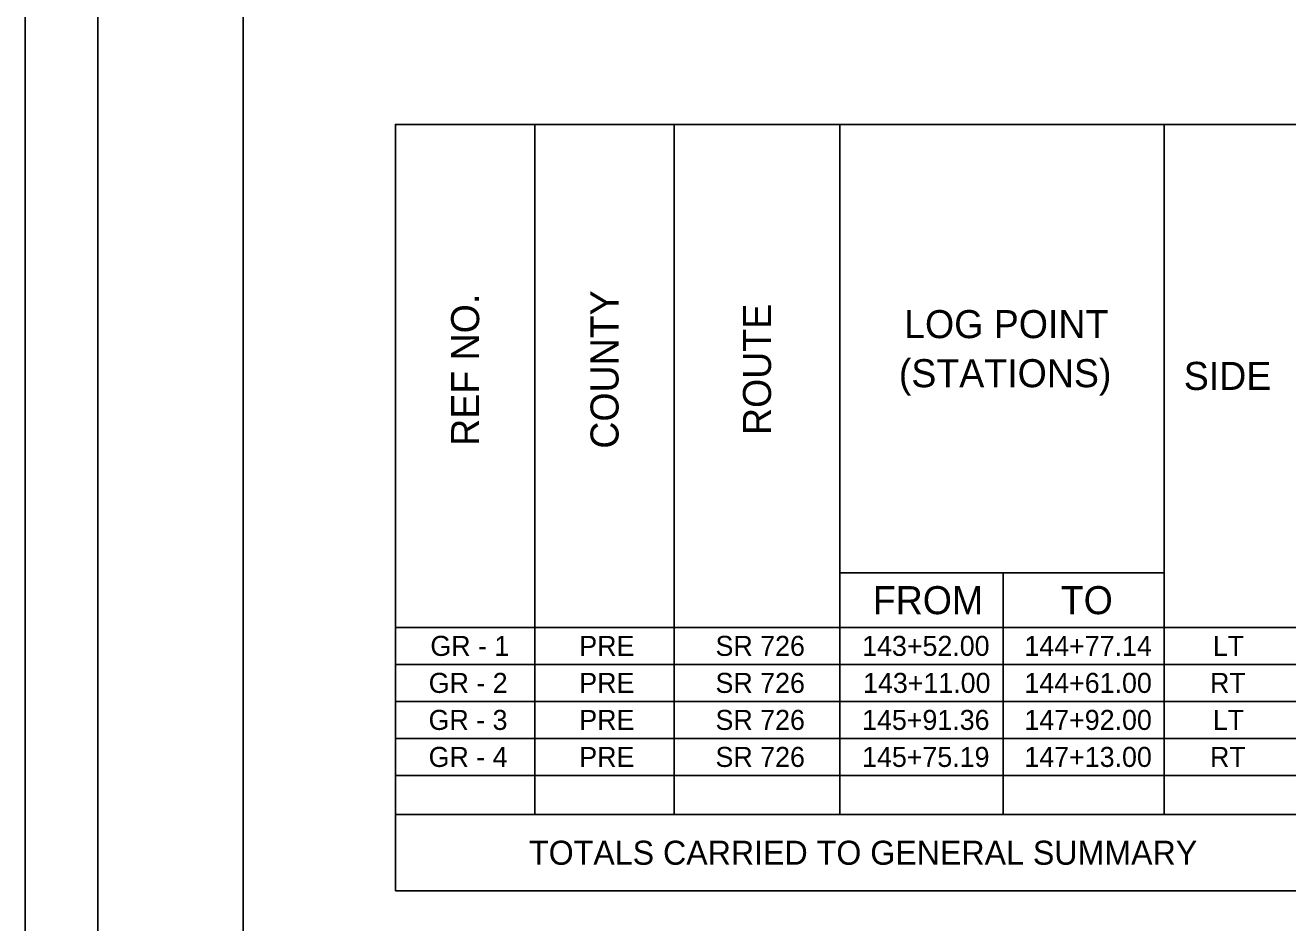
# Model space of a CAD drawing. Extents: x 0 to 34, y 0 to 22.
# Drawn here: x 0 to 8.69, y 9.63 to 15.82 of the extents above; entities that cross this region are included whole.
import ezdxf

# ---------------------------------------------------------------- set-up
doc = ezdxf.new("R2010")
doc.units = 0
for name, color, linetype in [('SH_Border', 7, 'Continuous'), ('SH_Cut_Line', 7, 'Continuous'), ('SH_Text', 7, 'Continuous')]:
    doc.layers.add(name, color=color, linetype=linetype)

msp = doc.modelspace()

# ---------------------------------------------------------------- linework, layer by layer
at = {"layer": 'SH_Border'}
for points in [[(0.5, 21.5), (1.5, 21.5), (1.5, 0.5), (0.5, 0.5)], [(1.5, 21.5), (33.5, 21.5), (33.5, 0.5), (1.5, 0.5)]]:
    msp.add_lwpolyline(points, close=True, dxfattribs=at)
at = {"layer": 'SH_Cut_Line'}
msp.add_lwpolyline([(0, 0), (34, 0), (34, 22), (0, 22)], close=True, dxfattribs=at)
at = {"layer": 'SH_Text'}
for p, q in [((2.5494, 15.1337), (22.3794, 15.1337)), ((2.5494, 15.1337), (2.5494, 9.8537)), ((3.5094, 15.1337), (3.5094, 10.3787)), ((4.4694, 15.1337), (4.4694, 10.3787)), ((5.6094, 15.1337), (5.6094, 10.3787)), ((7.8444, 15.1337), (7.8444, 10.3787)), ((5.6094, 12.0437), (7.8444, 12.0437)), ((6.7344, 12.0437), (6.7344, 10.3787)), ((2.5494, 11.6687), (22.3794, 11.6687)), ((2.5494, 11.4137), (22.3794, 11.4137)), ((2.5494, 11.1587), (22.3794, 11.1587)), ((2.5494, 10.9037), (22.3794, 10.9037)), ((2.5494, 10.6487), (22.3794, 10.6487)), ((2.5494, 10.3787), (22.3794, 10.3787)), ((2.5494, 9.8537), (22.3794, 9.8537))]:
    msp.add_line(p, q, dxfattribs=at)
for points in [[(2.5494, 15.1337), (2.5494, 15.1337), (2.5494, 15.1337), (2.5494, 15.1337)], [(2.5494, 15.1337), (2.5494, 15.1337), (2.5494, 14.8787), (2.5494, 14.8787)], [(2.5494, 15.1337), (2.5494, 15.1337), (2.5494, 14.8787), (2.5494, 14.8787)], [(2.5494, 15.1337), (2.5494, 15.1337), (2.5494, 14.8787), (2.5494, 14.8787)], [(2.5494, 15.1337), (2.5494, 15.1337), (2.5494, 14.8787), (2.5494, 14.8787)], [(2.5494, 15.1337), (2.5494, 15.1337), (2.5494, 14.8637), (2.5494, 14.8637)], [(2.5494, 15.1337), (3.5094, 15.1337), (3.5094, 15.1337), (2.5494, 15.1337)], [(2.5494, 15.1337), (3.5094, 15.1337), (3.5094, 15.1337), (2.5494, 15.1337)], [(2.5494, 15.1337), (3.6894, 15.1337), (3.6894, 15.1337), (2.5494, 15.1337)], [(2.5494, 15.1337), (3.6744, 15.1337), (3.6744, 15.1337), (2.5494, 15.1337)], [(2.5494, 15.1337), (3.6594, 15.1337), (3.6594, 15.1337), (2.5494, 15.1337)], [(2.5494, 15.1337), (3.4044, 15.1337), (3.4044, 15.1337), (2.5494, 15.1337)], [(2.5494, 15.1337), (2.5494, 15.1337), (2.5494, 15.1337), (2.5494, 15.1337)], [(2.5494, 15.1337), (3.7944, 15.1337), (3.7944, 15.1337), (2.5494, 15.1337)], [(2.5494, 15.1337), (3.7494, 15.1337), (3.7494, 15.1337), (2.5494, 15.1337)], [(2.5494, 15.1337), (3.7494, 15.1337), (3.7494, 15.1337), (2.5494, 15.1337)], [(2.5494, 15.1337), (3.7944, 15.1337), (3.7944, 15.1337), (2.5494, 15.1337)], [(2.5494, 15.1337), (3.8394, 15.1337), (3.8394, 15.1337), (2.5494, 15.1337)], [(2.5494, 15.1337), (3.8244, 15.1337), (3.8244, 15.1337), (2.5494, 15.1337)], [(2.5494, 15.1337), (3.8244, 15.1337), (3.8244, 15.1337), (2.5494, 15.1337)], [(2.5494, 15.1337), (4.1244, 15.1337), (4.1244, 15.1337), (2.5494, 15.1337)], [(2.5494, 15.1337), (5.9244, 15.1337), (5.9244, 15.1337), (2.5494, 15.1337)], [(2.5494, 15.1337), (3.5094, 15.1337), (3.5094, 15.1337), (2.5494, 15.1337)], [(2.5494, 15.1337), (3.5094, 15.1337), (3.5094, 15.1337), (2.5494, 15.1337)], [(2.5494, 15.1337), (3.6894, 15.1337), (3.6894, 15.1337), (2.5494, 15.1337)], [(2.5494, 15.1337), (3.6744, 15.1337), (3.6744, 15.1337), (2.5494, 15.1337)], [(2.5494, 15.1337), (3.6594, 15.1337), (3.6594, 15.1337), (2.5494, 15.1337)], [(2.5494, 15.1337), (3.4044, 15.1337), (3.4044, 15.1337), (2.5494, 15.1337)], [(2.5494, 15.1337), (2.5494, 15.1337), (2.5494, 15.1337), (2.5494, 15.1337)], [(2.5494, 15.1337), (3.7944, 15.1337), (3.7944, 15.1337), (2.5494, 15.1337)], [(2.5494, 15.1337), (3.7494, 15.1337), (3.7494, 15.1337), (2.5494, 15.1337)], [(2.5494, 15.1337), (3.7494, 15.1337), (3.7494, 15.1337), (2.5494, 15.1337)], [(2.5494, 15.1337), (3.7944, 15.1337), (3.7944, 15.1337), (2.5494, 15.1337)], [(2.5494, 15.1337), (3.8394, 15.1337), (3.8394, 15.1337), (2.5494, 15.1337)], [(2.5494, 15.1337), (3.8244, 15.1337), (3.8244, 15.1337), (2.5494, 15.1337)], [(2.5494, 15.1337), (3.8244, 15.1337), (3.8244, 15.1337), (2.5494, 15.1337)], [(2.5494, 15.1337), (4.1244, 15.1337), (4.1244, 15.1337), (2.5494, 15.1337)], [(2.5494, 15.1337), (5.9244, 15.1337), (5.9244, 15.1337), (2.5494, 15.1337)], [(2.5494, 15.1337), (3.5094, 15.1337), (3.5094, 15.1337), (2.5494, 15.1337)], [(2.5494, 15.1337), (3.5094, 15.1337), (3.5094, 15.1337), (2.5494, 15.1337)], [(2.5494, 15.1337), (3.6894, 15.1337), (3.6894, 15.1337), (2.5494, 15.1337)], [(2.5494, 15.1337), (3.6744, 15.1337), (3.6744, 15.1337), (2.5494, 15.1337)], [(2.5494, 15.1337), (3.6594, 15.1337), (3.6594, 15.1337), (2.5494, 15.1337)], [(2.5494, 15.1337), (3.4044, 15.1337), (3.4044, 15.1337), (2.5494, 15.1337)], [(2.5494, 15.1337), (2.5494, 15.1337), (2.5494, 15.1337), (2.5494, 15.1337)], [(2.5494, 15.1337), (3.7944, 15.1337), (3.7944, 15.1337), (2.5494, 15.1337)], [(2.5494, 15.1337), (3.7494, 15.1337), (3.7494, 15.1337), (2.5494, 15.1337)], [(2.5494, 15.1337), (3.7494, 15.1337), (3.7494, 15.1337), (2.5494, 15.1337)], [(2.5494, 15.1337), (3.7944, 15.1337), (3.7944, 15.1337), (2.5494, 15.1337)], [(2.5494, 15.1337), (3.8394, 15.1337), (3.8394, 15.1337), (2.5494, 15.1337)], [(2.5494, 15.1337), (3.8244, 15.1337), (3.8244, 15.1337), (2.5494, 15.1337)], [(2.5494, 15.1337), (3.8244, 15.1337), (3.8244, 15.1337), (2.5494, 15.1337)], [(2.5494, 15.1337), (4.1244, 15.1337), (4.1244, 15.1337), (2.5494, 15.1337)], [(2.5494, 15.1337), (5.9244, 15.1337), (5.9244, 15.1337), (2.5494, 15.1337)], [(2.5494, 15.1337), (2.5494, 15.1337), (2.5494, 15.1337), (2.5494, 15.1337)]]:
    msp.add_lwpolyline(points, close=True, dxfattribs=at)

# ---------------------------------------------------------------- texts
for s, p in [('REF NO.', (3.126, 12.9195)), ('COUNTY', (4.086, 12.8997)), ('ROUTE', (5.136, 12.9938))]:
    msp.add_text(s, height=0.1932, rotation=90, dxfattribs=at).set_placement(p)
for s, height, p in [('LOG POINT                 ', 0.1932, (6.0528, 13.6612)), ('(STATIONS)', 0.1932, (6.0164, 13.3231)), ('SIDE', 0.1932, (7.9787, 13.3046)), ('FROM', 0.1932, (5.8368, 11.7596)), ('TO', 0.1932, (7.1312, 11.7596)), ('GR - 1', 0.138, (2.7899, 11.4722)), ('PRE', 0.138, (3.8156, 11.4722)), ('SR 726', 0.138, (4.7539, 11.4722)), ('143+52.00', 0.138, (5.7637, 11.4722)), ('144+77.14', 0.138, (6.8812, 11.4722)), ('LT', 0.138, (8.1788, 11.4722)), ('GR - 2', 0.138, (2.7785, 11.2172)), ('PRE', 0.138, (3.8156, 11.2172)), ('SR 726', 0.138, (4.7539, 11.2172)), ('143+11.00', 0.138, (5.7701, 11.2172)), ('144+61.00', 0.138, (6.8812, 11.2172)), ('RT', 0.138, (8.1595, 11.2172)), ('GR - 3', 0.138, (2.7778, 10.9622)), ('PRE', 0.138, (3.8156, 10.9622)), ('SR 726', 0.138, (4.7539, 10.9622)), ('145+91.36', 0.138, (5.7634, 10.9622)), ('147+92.00', 0.138, (6.8812, 10.9622)), ('LT', 0.138, (8.1788, 10.9622)), ('GR - 4', 0.138, (2.7781, 10.7072)), ('PRE', 0.138, (3.8156, 10.7072)), ('SR 726', 0.138, (4.7539, 10.7072)), ('145+75.19', 0.138, (5.7633, 10.7072)), ('147+13.00', 0.138, (6.8812, 10.7072)), ('RT', 0.138, (8.1595, 10.7072)), ('TOTALS CARRIED TO GENERAL SUMMARY', 0.1656, (3.4695, 10.0334))]:
    msp.add_text(s, height=height, dxfattribs=at).set_placement(p)

doc.saveas('drawing.dxf')
